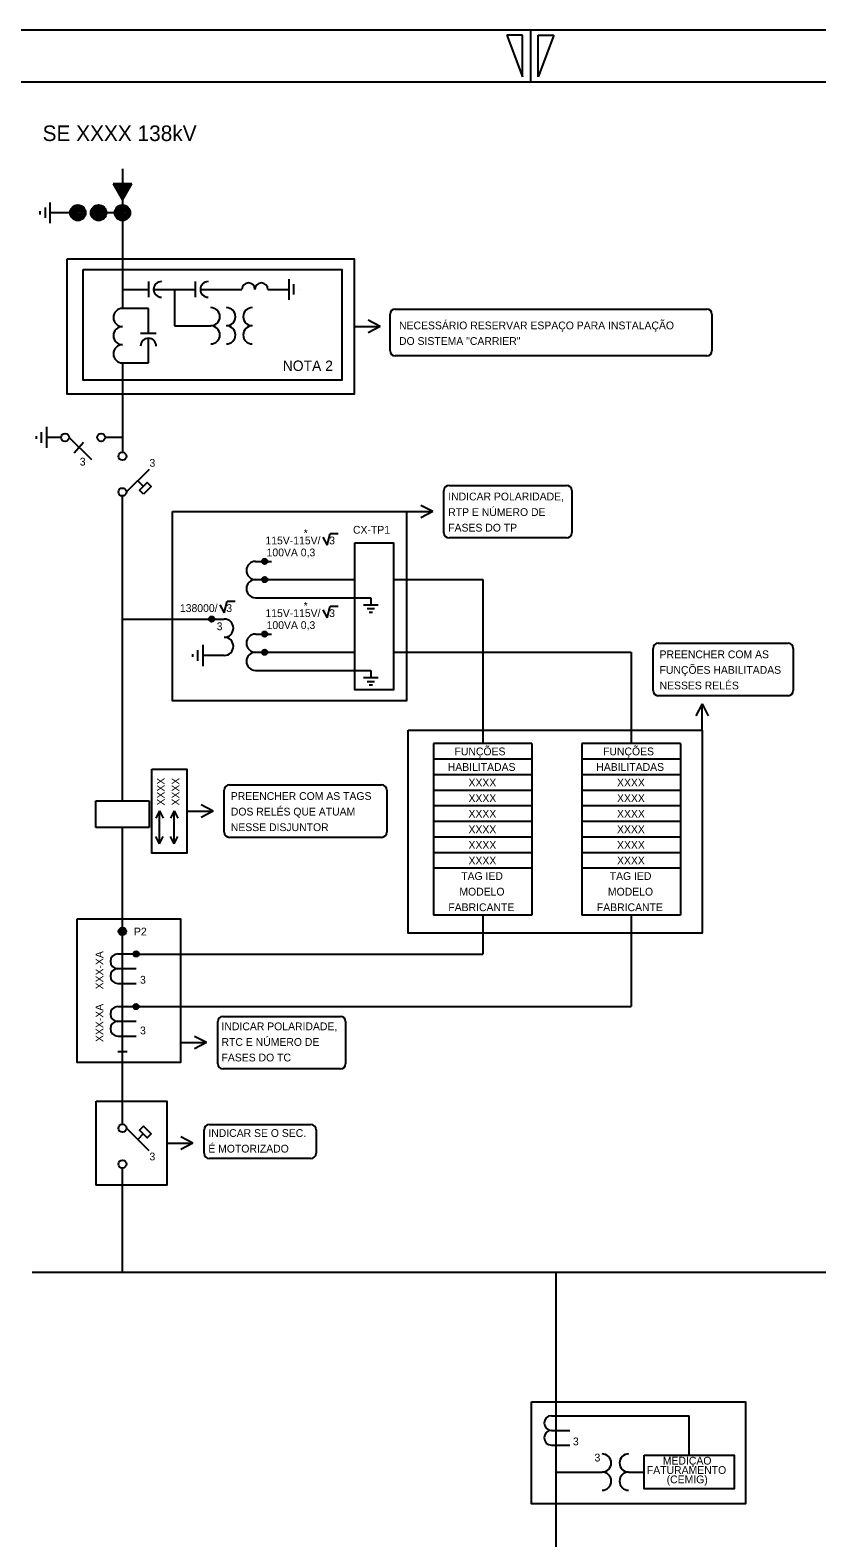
# Model space of a CAD drawing. Extents: x 501 to 1404, y 358 to 952.
# Drawn here: x 807.3 to 958.7, y 661.7 to 952 of the extents above; entities that cross this region are included whole.
import ezdxf

# ---------------------------------------------------------------- set-up
doc = ezdxf.new("R2010")
doc.units = 0
doc.layers.add('Level 1', color=7, linetype='Continuous')
doc.layers.add('New Level (0)', color=7, linetype='Continuous')

# ---------------------------------------------------------------- blocks, each defined once
blk = doc.blocks.new('_U3')
for p, q in [((-1.47, 0.42), (-0.62, -1.12)), ((-0.62, -1.12), (-0.07, 1.12)), ((-0.07, 1.12), (1.47, 1.12))]:
    blk.add_line(p, q)

msp = doc.modelspace()

# ---------------------------------------------------------------- linework, layer by layer
for p, q in [((825.05, 925.28), (825.05, 898.39)), ((826.86, 922.35), (823.24, 922.35)), ((823.24, 922.35), (825.05, 919.25)), ((826.86, 922.35), (823.24, 922.35)), ((826.68, 922.25), (823.42, 922.25)), ((823.42, 922.25), (825.05, 919.46)), ((826.5, 922.14), (823.6, 922.14)), ((823.6, 922.14), (825.05, 919.67)), ((826.32, 922.04), (823.78, 922.04)), ((823.78, 922.04), (825.05, 919.87)), ((826.14, 921.94), (823.96, 921.94)), ((823.96, 921.94), (825.05, 920.08)), ((825.96, 921.83), (824.15, 921.83)), ((824.15, 921.83), (825.05, 920.29)), ((825.77, 921.73), (824.33, 921.73)), ((824.33, 921.73), (825.05, 920.49)), ((825.59, 921.63), (824.51, 921.63)), ((824.51, 921.63), (825.05, 920.7)), ((825.41, 921.52), (824.69, 921.52)), ((824.69, 921.52), (825.05, 920.9)), ((825.23, 921.42), (824.87, 921.42)), ((824.87, 921.42), (825.05, 921.11)), ((825.05, 919.25), (826.86, 922.35)), ((825.05, 922.35), (825.05, 919.25)), ((825.05, 919.46), (826.68, 922.25)), ((825.05, 919.67), (826.5, 922.14)), ((825.05, 919.87), (826.32, 922.04)), ((825.05, 920.08), (826.14, 921.94)), ((825.05, 920.29), (825.96, 921.83)), ((825.05, 920.49), (825.77, 921.73)), ((825.05, 920.7), (825.59, 921.63)), ((825.05, 920.9), (825.41, 921.52)), ((825.05, 921.11), (825.23, 921.42)), ((810.15, 917.8), (810.15, 915.8)), ((811.15, 914.8), (811.15, 918.8)), ((809.15, 917.1), (809.15, 916.5)), ((809.15, 916.8), (809.15, 916.8)), ((812.46, 916.8), (811.15, 916.8)), ((816.46, 916.8), (812.46, 916.8)), ((825.05, 916.8), (820.46, 916.8)), ((825.05, 887.89), (825.05, 870.68)), ((808.41, 873.8), (808.41, 873.27)), ((809.43, 872.54), (809.43, 874.59)), ((810.45, 875.61), (810.45, 871.52)), ((813.24, 873.56), (810.45, 873.56)), ((819.12, 869.23), (814.78, 873.56)), ((815.77, 870.62), (817.57, 872.64)), ((825.05, 873.56), (821.72, 873.56)), ((830.16, 867.38), (825.82, 863.05)), ((829.05, 864.15), (827.99, 865.21)), ((825.05, 803.57), (825.05, 862.24)), ((850.65, 849.69), (853.75, 849.69)), ((850.65, 846.19), (869.78, 846.19)), ((877.26, 846.19), (894.41, 846.19)), ((850.65, 842.69), (872.87, 842.69)), ((872.87, 842.69), (872.87, 841.29)), ((874.27, 841.29), (871.47, 841.29)), ((872.17, 840.59), (873.57, 840.59)), ((872.53, 839.89), (873.22, 839.89)), ((825.05, 838.59), (844.65, 838.59)), ((840.55, 833.64), (840.55, 829.54)), ((850.65, 835.7), (853.75, 835.7)), ((838.51, 831.83), (838.51, 831.29)), ((839.53, 830.56), (839.53, 832.61)), ((844.65, 831.59), (840.55, 831.59)), ((850.65, 832.2), (853.75, 832.2)), ((850.65, 832.2), (869.78, 832.2)), ((877.26, 832.2), (923.01, 832.2)), ((850.65, 828.7), (872.87, 828.7)), ((874.27, 827.3), (871.47, 827.3)), ((872.87, 828.7), (872.87, 827.3)), ((872.17, 826.6), (873.57, 826.6)), ((872.53, 825.9), (873.22, 825.9)), ((903.9, 814.61), (884.92, 814.61)), ((884.92, 814.61), (884.92, 781.61)), ((903.9, 814.61), (903.9, 781.61)), ((932.5, 814.61), (913.52, 814.61)), ((913.52, 814.61), (913.52, 781.61)), ((932.5, 814.61), (932.5, 781.61)), ((903.9, 811.61), (884.92, 811.61)), ((932.5, 811.61), (913.52, 811.61)), ((903.9, 808.61), (884.92, 808.61)), ((932.5, 808.61), (913.52, 808.61)), ((903.9, 805.61), (884.92, 805.61)), ((932.5, 805.61), (913.52, 805.61)), ((819.93, 798.45), (819.93, 803.57)), ((819.93, 803.57), (830.17, 803.57)), ((830.17, 803.57), (830.17, 798.45)), ((832.17, 801.69), (831.46, 800.27)), ((832.17, 795.32), (832.17, 801.69)), ((832.17, 801.69), (832.87, 800.27)), ((835.02, 801.69), (834.31, 800.27)), ((835.02, 795.32), (835.02, 801.69)), ((835.02, 801.69), (835.72, 800.27)), ((903.9, 802.61), (884.92, 802.61)), ((932.5, 802.61), (913.52, 802.61)), ((830.17, 798.45), (819.93, 798.45)), ((825.05, 741.35), (825.05, 798.45)), ((903.9, 799.61), (884.92, 799.61)), ((932.5, 799.61), (913.52, 799.61)), ((832.17, 795.32), (831.46, 796.74)), ((832.17, 795.32), (832.87, 796.74)), ((835.02, 795.32), (834.31, 796.74)), ((835.02, 795.32), (835.72, 796.74)), ((903.9, 796.61), (884.92, 796.61)), ((903.9, 796.61), (884.92, 796.61)), ((932.5, 796.61), (913.52, 796.61)), ((932.5, 796.61), (913.52, 796.61)), ((903.9, 793.61), (884.92, 793.61)), ((932.5, 793.61), (913.52, 793.61)), ((903.9, 790.61), (884.92, 790.61)), ((932.5, 790.61), (913.52, 790.61)), ((903.9, 781.61), (884.92, 781.61)), ((932.5, 781.61), (913.52, 781.61)), ((824.14, 774.12), (827.68, 774.12)), ((827.68, 774.11), (894.41, 774.11)), ((824.14, 771.29), (827.68, 771.29)), ((824.14, 768.46), (827.68, 768.46)), ((824.14, 763.98), (827.68, 763.98)), ((827.68, 763.98), (923.01, 763.98)), ((824.14, 761.15), (827.68, 761.15)), ((824.14, 758.32), (827.68, 758.32)), ((830.16, 736.24), (825.82, 740.58)), ((829.05, 739.47), (827.99, 738.41)), ((825.05, 712.81), (825.05, 732.91)), ((1009.5, 712.81), (807.64, 712.81)), ((908.57, 654.53), (908.57, 712.81)), ((907.65, 685.23), (911.19, 685.23)), ((911.19, 685.23), (934.18, 685.23)), ((907.65, 682.4), (911.19, 682.4)), ((907.65, 679.57), (911.19, 679.57)), ((908.57, 674.38), (917.4, 674.38)), ((922.5, 674.38), (925.51, 674.38))]:
    msp.add_line(p, q)
for points in [[(829.08, 862.65), (828.31, 863.42), (829.79, 864.89), (830.56, 864.12)], [(829.08, 740.98), (828.31, 740.21), (829.79, 738.73), (830.56, 739.5)]]:
    msp.add_lwpolyline(points, close=True)
for centre, radius in [((816.46, 916.8), 1.5), ((816.46, 916.8), 1.25), ((816.46, 916.8), 1), ((816.46, 916.8), 0.75), ((816.46, 916.8), 0.5), ((820.46, 916.8), 1.5), ((820.46, 916.8), 1.25), ((820.46, 916.8), 1), ((820.46, 916.8), 0.75), ((820.46, 916.8), 0.5), ((825.05, 916.8), 1.5), ((825.05, 916.8), 1.25), ((825.05, 916.8), 1), ((825.05, 916.8), 0.75), ((825.05, 916.8), 0.5), ((816.46, 916.8), 0.25), ((820.46, 916.8), 0.25), ((825.05, 916.8), 0.25), ((814.01, 873.56), 0.768), ((820.95, 873.56), 0.768), ((825.05, 869.92), 0.768), ((825.05, 863.05), 0.768), ((852.44, 849.69), 0.511), ((852.44, 849.69), 0.288), ((852.44, 846.19), 0.511), ((852.44, 846.19), 0.288), ((842.21, 838.58), 0.511), ((842.21, 838.58), 0.288), ((852.45, 835.7), 0.511), ((852.45, 835.7), 0.288), ((852.45, 832.2), 0.511), ((852.45, 832.2), 0.288), ((825.04, 778.45), 0.729), ((825.05, 778.45), 0.511), ((825.05, 778.45), 0.288), ((827.68, 774.12), 0.511), ((827.68, 774.12), 0.288), ((827.67, 763.98), 0.511), ((827.67, 763.98), 0.288), ((825.05, 740.58), 0.768), ((825.05, 733.67), 0.768)]:
    msp.add_circle(centre, radius)
for centre, radius, start, end in [((850.65, 847.94), 1.75, 90, 270), ((850.65, 844.44), 1.75, 90, 270), ((844.65, 836.84), 1.75, 270, 90), ((844.65, 833.34), 1.75, 270, 90), ((850.65, 833.95), 1.75, 90, 270), ((850.65, 830.45), 1.75, 90, 270), ((824.14, 772.7), 1.42, 90, 270), ((824.14, 769.87), 1.42, 90, 270), ((824.14, 762.56), 1.42, 90, 270), ((824.14, 759.73), 1.42, 90, 270), ((907.65, 683.81), 1.42, 90, 270), ((907.65, 680.98), 1.42, 90, 270), ((917.4, 676.13), 1.75, 270, 90), ((922.5, 676.13), 1.75, 90, 270), ((917.4, 672.63), 1.75, 270, 90), ((922.5, 672.63), 1.75, 90, 270)]:
    msp.add_arc(centre, radius, start, end)
at = {"layer": 'Level 1'}
for p, q in [((830.05, 903.54), (830.05, 900.54)), ((839.05, 903.54), (839.05, 900.54)), ((857.05, 904.04), (857.05, 900.04)), ((858.05, 901.04), (858.05, 903.04)), ((825.05, 902.04), (830.05, 902.04)), ((831.05, 902.04), (839.05, 902.04)), ((835.05, 902.04), (835.05, 895.04)), ((840.05, 902.04), (848.05, 902.04)), ((853.05, 902.04), (857.05, 902.04)), ((859.05, 902.04), (859.05, 902.04)), ((830.05, 898.39), (825.05, 898.39)), ((830.05, 893.64), (830.05, 898.39)), ((835.05, 895.04), (842.05, 895.04)), ((828.55, 893.64), (831.55, 893.64)), ((830.05, 887.89), (830.05, 892.64)), ((825.05, 887.89), (830.05, 887.89))]:
    msp.add_line(p, q, dxfattribs=at)
for centre, radius, start, end in [((832.55, 902.04), 1.5, 90, 270), ((841.55, 902.04), 1.5, 90, 270), ((849.3, 902.04), 1.25, 0, 180), ((851.8, 902.04), 1.25, 0, 180), ((825.05, 896.64), 1.75, 90, 270), ((842.05, 896.79), 1.75, 270, 90), ((845.05, 896.79), 1.75, 270, 90), ((850.05, 896.79), 1.75, 90, 270), ((825.05, 893.14), 1.75, 90, 270), ((842.05, 893.29), 1.75, 270, 90), ((845.05, 893.29), 1.75, 270, 90), ((850.05, 893.29), 1.75, 90, 270), ((825.05, 889.64), 1.75, 90, 270), ((830.05, 891.14), 1.5, 0, 180)]:
    msp.add_arc(centre, radius, start, end, dxfattribs=at)
at = {"layer": 'New Level (0)'}
for p, q in [((1403.58, 951.96), (562.58, 951.96)), ((1403.58, 951.96), (562.58, 951.96)), ((902.08, 950.96), (899.08, 950.96)), ((899.08, 950.96), (902.08, 942.96)), ((902.08, 942.96), (902.08, 950.96)), ((903.58, 951.96), (903.58, 941.96)), ((905.08, 942.96), (905.08, 950.96)), ((905.08, 950.96), (908.08, 950.96)), ((908.08, 950.96), (905.08, 942.96)), ((1393.58, 941.96), (572.58, 941.96)), ((876.58, 890.24), (876.58, 897.27)), ((877.58, 898.27), (907.67, 898.27)), ((907.67, 898.27), (937.54, 898.27)), ((938.54, 897.27), (938.54, 890.24)), ((869.65, 894.9), (874.68, 894.9)), ((874.68, 894.9), (872.38, 896.11)), ((874.68, 894.9), (872.38, 893.69)), ((937.54, 889.24), (877.58, 889.24)), ((886.94, 855.21), (886.94, 863.32)), ((887.94, 864.32), (895.29, 864.32)), ((895.29, 864.32), (910.56, 864.32)), ((911.56, 863.32), (911.56, 855.21)), ((879.75, 859.27), (884.78, 859.27)), ((884.78, 859.27), (882.49, 860.48)), ((884.78, 859.27), (882.49, 858.06)), ((910.56, 854.21), (887.94, 854.21)), ((894.41, 846.19), (894.41, 814.61)), ((928.2, 833.95), (935.55, 833.95)), ((935.55, 833.95), (953.21, 833.95)), ((923.01, 832.2), (923.01, 814.61)), ((927.2, 824.84), (927.2, 832.95)), ((954.21, 832.95), (954.21, 824.84)), ((953.21, 823.84), (928.2, 823.84)), ((936.64, 822.24), (935.43, 819.95)), ((936.64, 817.22), (936.64, 822.24)), ((936.64, 822.24), (937.85, 819.95)), ((844.64, 797.56), (844.64, 805.67)), ((845.64, 806.67), (853, 806.67)), ((853, 806.67), (874.94, 806.67)), ((875.94, 805.67), (875.94, 797.56)), ((837.46, 801.62), (842.49, 801.62)), ((842.49, 801.62), (840.19, 802.82)), ((842.49, 801.62), (840.19, 800.41)), ((874.94, 796.56), (845.64, 796.56)), ((894.41, 781.61), (894.41, 774.11)), ((923.01, 781.61), (923.01, 763.98)), ((843.41, 752.99), (843.41, 761.1)), ((844.41, 762.1), (851.76, 762.1)), ((851.76, 762.1), (867.02, 762.1)), ((868.02, 761.1), (868.02, 752.99)), ((841.25, 757.05), (838.95, 758.26)), ((824.15, 755.37), (825.95, 755.37)), ((836.22, 757.05), (841.25, 757.05)), ((841.25, 757.05), (838.95, 755.84)), ((867.02, 751.99), (844.41, 751.99)), ((840.75, 735.74), (840.75, 740.29)), ((841.75, 741.29), (849.1, 741.29)), ((849.1, 741.29), (861.33, 741.29)), ((862.33, 740.29), (862.33, 735.74)), ((833.56, 737.69), (838.59, 737.69)), ((838.59, 737.69), (836.3, 738.9)), ((838.59, 737.69), (836.3, 736.48)), ((861.33, 734.74), (841.75, 734.74)), ((934.18, 677.61), (934.18, 685.23))]:
    msp.add_line(p, q, dxfattribs=at)
for points in [[(814.37, 907.95), (869.65, 907.95), (869.65, 881.85), (814.37, 881.85)], [(817.51, 905.86), (867.26, 905.86), (867.26, 884.57), (817.51, 884.57)], [(834.7, 859.27), (879.75, 859.27), (879.75, 822.86), (834.7, 822.86)], [(869.78, 853.29), (877.26, 853.29), (877.26, 824.99), (869.78, 824.99)], [(880.03, 817.22), (936.64, 817.22), (936.64, 778.15), (880.03, 778.15)], [(830.68, 809.72), (837.46, 809.72), (837.46, 793.51), (830.68, 793.51)], [(816.32, 780.91), (836.22, 780.91), (836.22, 753.23), (816.32, 753.23)], [(820.01, 745.8), (833.56, 745.8), (833.56, 729.58), (820.01, 729.58)], [(903.82, 687.89), (944.99, 687.89), (944.99, 668.28), (903.82, 668.28)], [(925.51, 677.61), (942.85, 677.61), (942.85, 671.14), (925.51, 671.14)]]:
    msp.add_lwpolyline(points, close=True, dxfattribs=at)
for centre, start, end in [((877.58, 897.27), 90, 180), ((937.54, 897.27), 0, 90), ((877.58, 890.24), 180, 270), ((937.54, 890.24), 270, 0), ((887.94, 863.32), 90, 180), ((910.56, 863.32), 0, 90), ((887.94, 855.21), 180, 270), ((910.56, 855.21), 270, 0), ((928.2, 832.95), 90, 180), ((953.21, 832.95), 0, 90), ((928.2, 824.84), 180, 270), ((953.21, 824.84), 270, 0), ((845.64, 805.67), 90, 180), ((874.94, 805.67), 0, 90), ((845.64, 797.56), 180, 270), ((874.94, 797.56), 270, 0), ((844.41, 761.1), 90, 180), ((867.02, 761.1), 0, 90), ((844.41, 752.99), 180, 270), ((867.02, 752.99), 270, 0), ((841.75, 740.29), 90, 180), ((861.33, 740.29), 0, 90), ((841.75, 735.74), 180, 270), ((861.33, 735.74), 270, 0)]:
    msp.add_arc(centre, 1, start, end, dxfattribs=at)

# ---------------------------------------------------------------- block references
for p in [(865.08, 853.94), (845.26, 840.92), (865.08, 839.95)]:
    msp.add_blockref('_U3', p)

# ---------------------------------------------------------------- texts
for s, height, p in [('SE XXXX 138kV', 3, (809.67, 930.61)), ('NECESSÁRIO RESERVAR ESPAÇO PARA INSTALAÇÃO ', 1.5, (878.3, 894.36)), ('DO SISTEMA "CARRIER"', 1.5, (878.3, 891.36)), ('NOTA 2', 2, (855.91, 886.35)), ('3', 1.5, (816.83, 868.14)), ('3', 1.5, (830.25, 867.91)), ('INDICAR POLARIDADE, ', 1.5, (887.77, 861.43)), ('RTP E NÚMERO DE ', 1.5, (887.77, 858.43)), ('CX-TP1', 1.5, (869.43, 855.02)), ('FASES DO TP', 1.5, (887.77, 855.43)), ('115V-115V/   3', 1.5, (852.58, 852.97)), ('*', 1.5, (859.94, 854.39)), ('100VA 0,3', 1.5, (852.8, 850.66)), ('*', 1.5, (859.94, 840.4)), ('138000/   3', 1.5, (836.11, 839.95)), ('115V-115V/   3', 1.5, (852.58, 838.98)), ('3', 1.5, (843.19, 836.44)), ('100VA 0,3', 1.5, (852.8, 836.67)), ('PREENCHER COM AS ', 1.5, (928.46, 831.05)), ('FUNÇÕES HABILITADAS ', 1.5, (928.46, 828.05)), ('NESSES RELÉS', 1.5, (928.46, 825.05)), ('FUNÇÕES ', 1.5, (888.98, 812.36)), ('FUNÇÕES ', 1.5, (917.58, 812.36)), ('HABILITADAS', 1.5, (887.68, 809.36)), ('HABILITADAS', 1.5, (916.28, 809.36)), ('XXXX', 1.5, (891.67, 806.36)), ('XXXX', 1.5, (920.27, 806.36)), ('PREENCHER COM AS TAGS ', 1.5, (845.91, 803.77)), ('XXXX', 1.5, (891.67, 803.36)), ('XXXX', 1.5, (920.27, 803.36)), ('DOS RELÉS QUE ATUAM ', 1.5, (845.91, 800.77)), ('XXXX', 1.5, (891.67, 800.36)), ('XXXX', 1.5, (920.27, 800.36)), ('NESSE DISJUNTOR', 1.5, (845.91, 797.77)), ('XXXX', 1.5, (891.67, 797.36)), ('XXXX', 1.5, (920.27, 797.36)), ('XXXX', 1.5, (891.67, 794.36)), ('XXXX', 1.5, (920.27, 794.36)), ('XXXX', 1.5, (891.67, 791.36)), ('XXXX', 1.5, (920.27, 791.36)), ('TAG IED', 1.5, (890.27, 788.36)), ('TAG IED', 1.5, (918.87, 788.36)), ('MODELO', 1.5, (889.92, 785.36)), ('MODELO', 1.5, (918.52, 785.36)), ('FABRICANTE', 1.5, (887.79, 782.36)), ('FABRICANTE', 1.5, (916.39, 782.36)), ('P2', 1.5, (827.26, 777.68)), ('3', 1.5, (828.43, 768.4)), ('INDICAR POLARIDADE, ', 1.5, (844.12, 759.43)), ('3', 1.5, (828.43, 758.64)), ('RTC E NÚMERO DE ', 1.5, (844.12, 756.43)), ('FASES DO TC', 1.5, (844.12, 753.43)), ('INDICAR SE O SEC. ', 1.5, (841.58, 738.89)), ('É MOTORIZADO', 1.5, (841.58, 735.89)), ('3', 1.5, (830.25, 734.38)), ('3', 1.5, (911.78, 679.53)), ('3', 1.5, (915.94, 676.42)), ('MEDIÇÃO', 1.5, (929.09, 675.82)), ('FATURAMENTO', 1.5, (926.02, 674.02)), ('(CEMIG)', 1.5, (929.83, 672.22))]:
    msp.add_text(s, height=height).set_placement(p)
for s, p in [('XXXX', (833.17, 802.69)), ('XXXX', (836.02, 802.69)), ('XXX-XA', (821.36, 767.3)), ('XXX-XA', (821.36, 757.16))]:
    msp.add_text(s, height=1.5, rotation=90).set_placement(p)

doc.saveas('drawing.dxf')
